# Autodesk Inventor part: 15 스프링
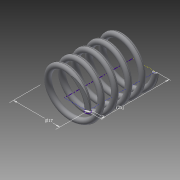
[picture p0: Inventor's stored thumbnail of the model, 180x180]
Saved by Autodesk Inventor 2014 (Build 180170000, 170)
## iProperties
Created: 2016-03
Part Number: 15 스프링
Material: 일반
Document SubType Name: Modeling
Designer: SEC
Density: 1 g/cm^3
Appearance: 기본값
Author: SEC
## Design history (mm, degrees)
sketch "스케치1"
  geometry: L1 (0, 0)-(8.5, 0); L2 (8.5, 0)-(8.5, 20.5); L3 (8.5, 20.5)-(0, 20.5); L4 (0, 20.5)-(0, 0); C1 r 1 at (8.5, 0)
  constraints: 8 end point, 2 parallel, 1 centre point, 1 coincident, 1 horizontal, 1 perpendicular
  dimensions: "d0" = 17 diameter of L2 L4; "d1" = 20.5 distance of L1.end L2.end (derived); "d2" = 2 diameter of C1
feature "코일1" pitch "d3" = 10; turns "d5" = 5; dims "d4" = 20.5 (= d1), "d6" = 0, angle "d7" = 90 deg, angle "d8" = 90 deg, "d9" = 0, "d10" = 0
sketch "스케치2"
  geometry: L1 (-7.5, 0)-(-9.5, 0) reference; 1 further point
  constraints: 1 horizontal alignment
extrude "돌출1" cut sketch "스케치2" stored distance "d11" = 10; taper "d12" = 0 deg
node "작업 평면1"
sketch "스케치3"
  geometry: L1 (-9.5, 0)-(-7.5, 0) reference; 1 further point
  constraints: 1 horizontal alignment
extrude "돌출2" cut sketch "스케치3" stored distance "d13" = 10; taper "d14" = 0 deg
node "솔리드1"
node "절단 모서리 투영1"
node "절단 모서리 투영2"
